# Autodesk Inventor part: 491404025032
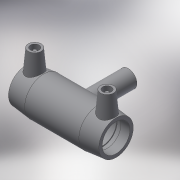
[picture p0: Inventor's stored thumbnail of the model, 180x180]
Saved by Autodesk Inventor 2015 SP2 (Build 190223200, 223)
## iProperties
Created: 2017-06
Part Number: 491404025032
Material: Generic
Description: PLASSON REDUCING TEE 25x32x25
Document SubType Name: Modeling
Designer: KIM
Mass: 57.3761 g
Surface Area: 241.06 cm^2
Volume: 57.3761 cm^3
Density: 1 g/cm^3
Appearance: Default
Author: KIM
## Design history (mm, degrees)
derived "491404.ipt"
feature "Solid1::491404.ipt"
tag "TaggingFeature1"
body "Solid1"
other parameters: "d0" = 104, "d1" = 25, "d2" = 44, "d3" = 39, "d4" = 20.8, "d5" = 39.6, "d6" = 23.75, "d7" = 25, "d8" = 168 deg, "d10" = 15.6, "d11" = 5.2, "d13" = 104, "d14" = 17.6296, "d17" = 22.5, "d18" = 25, "d19" = 3.52592, "d20" = 168 deg, "d22" = 40.92, "d23" = 44, "d25" = 135 deg, "d26" = 72.8, "d29" = 43, "d30" = 15, "d31" = 41.6, "d34" = 5 deg, "d35" = 15, "d39" = 5 deg, "d41" = 4, "d42" = 14, "d43" = 0, "d45" = 4, "d46" = 6, "d47" = 0, "d48" = -74, "d49" = 32, "d51" = 0, "d52" = 25.6, "d54" = 0, "d55" = 39.6, "d56" = 44, "d57" = 36.4, "d58" = 135 deg, "d59" = 39, "d60" = 39, "d61" = 135 deg, "d62" = 74, "d72" = 47.32, "d73" = 23.66, "d74" = -74, "d75" = 33.6, "d77" = 0, "d78" = 25.6, "d80" = 0, "d81" = 32, "d82" = 52, "d83" = 0, "d84" = 3, "d85" = 0, "d86" = 13, "d87" = 40.1016, "d88" = 5.2, "d89" = 3, "d90" = 0, "d_" = 25, "L_" = 104, "L_1" = 39, "D_" = 44, "A_" = 43, "d_2" = 12, "H_" = 74, "d_1" = 32
